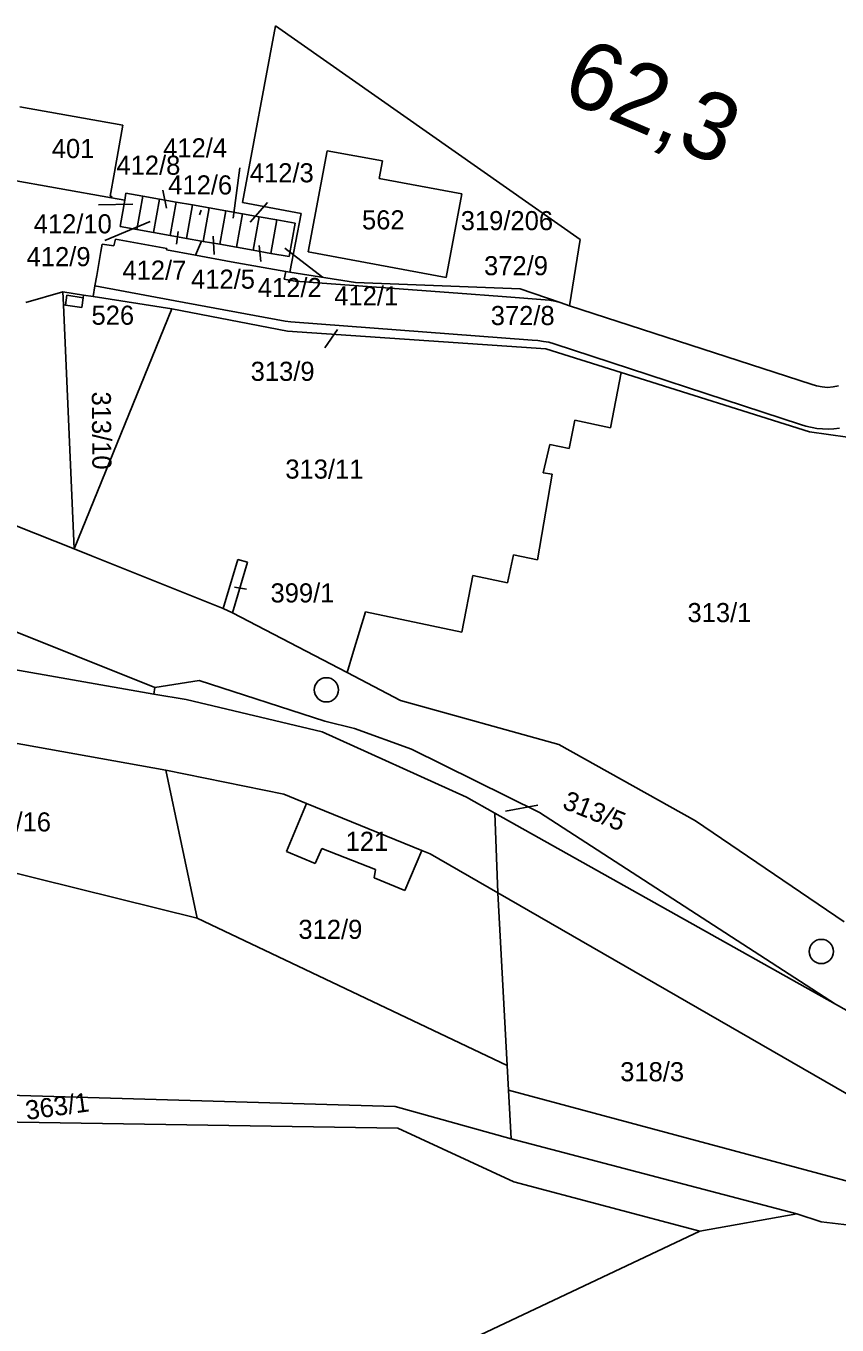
# Model space of a CAD drawing. Extents: x -805826 to -803822, y -1165880 to -1164382.
# Drawn here: x -805258.6 to -805114.2, y -1165078.1 to -1164846.8 of the extents above; entities that cross this region are included whole.
import ezdxf

# ---------------------------------------------------------------- set-up
doc = ezdxf.new("R2010")
doc.units = 0
for name, color, linetype in [('kilometráž - 2880', 7, 'Continuous'), ('kn_celek - Cisla parcel pomocna', 7, 'Continuous'), ('kn_celek - Cisla pozemkovych parcel', 7, 'Continuous'), ('kn_celek - Cisla stavebnich parcel', 7, 'Continuous'), ('kn_celek - Hranice parcel', 7, 'Continuous'), ('kn_celek - Vnitrni kresby', 7, 'Continuous'), ('plochy - SZDC', 7, 'Continuous')]:
    doc.layers.add(name, color=color, linetype=linetype)

msp = doc.modelspace()

# ---------------------------------------------------------------- linework, layer by layer
at = {"layer": 'kilometráž - 2880'}
for centre in [(-805205.12, -1164965.01), (-805117.01, -1165011.6)]:
    msp.add_circle(centre, 2.16, dxfattribs=at)
at = {"layer": 'kn_celek - Cisla parcel pomocna'}
for p, q in [((-805221.73, -1164881), (-805220.53, -1164872.06)), ((-805233.6, -1164879.25), (-805234.23, -1164876.02)), ((-805239.56, -1164878.53), (-805245.71, -1164878.63)), ((-805218.68, -1164881.73), (-805215.63, -1164878.22)), ((-805227.72, -1164880.44), (-805227.4, -1164879.59)), ((-805236.52, -1164881.64), (-805244.57, -1164885.01)), ((-805231.49, -1164883.37), (-805231.79, -1164885.66)), ((-805225.27, -1164884.21), (-805225.08, -1164887.5)), ((-805217.06, -1164885.88), (-805216.77, -1164888.73)), ((-805212.54, -1164886.36), (-805205.8, -1164891.53)), ((-805203.15, -1164900.87), (-805205.4, -1164904.12)), ((-805221.47, -1164946.71), (-805219.37, -1164947.07)), ((-805173.22, -1164986.64), (-805167.5, -1164985.52))]:
    msp.add_line(p, q, dxfattribs=at)
at = {"layer": 'kn_celek - Hranice parcel'}
for p, q in [((-805214.18, -1164846.8), (-805220.07, -1164878.24)), ((-805214.18, -1164846.8), (-805159.93, -1164884.85)), ((-805259.71, -1164861.19), (-805241.37, -1164864.44)), ((-805241.37, -1164864.44), (-805242.86, -1164872.82)), ((-805208.34, -1164887.04), (-805204.99, -1164869.01)), ((-805204.99, -1164869.01), (-805195.15, -1164870.83)), ((-805195.15, -1164870.83), (-805195.73, -1164873.93)), ((-805243.35, -1164877.38), (-805262, -1164874.09)), ((-805242.86, -1164872.82), (-805243.62, -1164877.13)), ((-805195.73, -1164873.93), (-805181, -1164876.67)), ((-805240.8, -1164876.56), (-805241.02, -1164877.84)), ((-805240.8, -1164876.56), (-805237.8, -1164877.09)), ((-805181, -1164876.67), (-805183.78, -1164891.59)), ((-805243.62, -1164877.13), (-805243.3, -1164877.19)), ((-805243.3, -1164877.19), (-805243.35, -1164877.38)), ((-805243.35, -1164877.38), (-805241.02, -1164877.84)), ((-805241.02, -1164877.84), (-805241.86, -1164882.53)), ((-805237.8, -1164877.09), (-805238.86, -1164883.05)), ((-805237.8, -1164877.09), (-805234.85, -1164877.62)), ((-805234.85, -1164877.62), (-805235.9, -1164883.57)), ((-805234.85, -1164877.62), (-805231.88, -1164878.15)), ((-805231.88, -1164878.15), (-805232.95, -1164884.11)), ((-805231.88, -1164878.15), (-805228.93, -1164878.67)), ((-805228.93, -1164878.67), (-805230, -1164884.63)), ((-805228.93, -1164878.67), (-805226, -1164879.2)), ((-805226, -1164879.2), (-805227.04, -1164885.15)), ((-805226, -1164879.2), (-805223.02, -1164879.73)), ((-805220.07, -1164878.24), (-805209.64, -1164880.21)), ((-805224.08, -1164885.68), (-805223.02, -1164879.73)), ((-805223.02, -1164879.73), (-805220.05, -1164880.25)), ((-805221.12, -1164886.2), (-805220.05, -1164880.25)), ((-805220.05, -1164880.25), (-805217.1, -1164880.78)), ((-805217.1, -1164880.78), (-805218.17, -1164886.72)), ((-805217.1, -1164880.78), (-805213.92, -1164881.34)), ((-805213.92, -1164881.34), (-805214.99, -1164887.29)), ((-805213.92, -1164881.34), (-805210.68, -1164881.9)), ((-805209.64, -1164880.21), (-805211.62, -1164890.64)), ((-805238.86, -1164883.05), (-805241.86, -1164882.53)), ((-805238.86, -1164883.05), (-805235.9, -1164883.57)), ((-805235.9, -1164883.57), (-805232.95, -1164884.11)), ((-805210.68, -1164881.9), (-805211.74, -1164887.86)), ((-805245.02, -1164885.65), (-805245.28, -1164886.98)), ((-805242.96, -1164885.95), (-805245.02, -1164885.65)), ((-805242.64, -1164884.75), (-805242.96, -1164885.95)), ((-805233.53, -1164886.43), (-805242.64, -1164884.75)), ((-805232.95, -1164884.11), (-805230, -1164884.63)), ((-805230, -1164884.63), (-805227.34, -1164885.1)), ((-805227.34, -1164885.1), (-805228.45, -1164887.59)), ((-805227.34, -1164885.1), (-805227.04, -1164885.15)), ((-805227.04, -1164885.15), (-805224.08, -1164885.68)), ((-805221.12, -1164886.2), (-805224.08, -1164885.68)), ((-805159.93, -1164884.85), (-805161.83, -1164896.62)), ((-805245.28, -1164886.98), (-805246.01, -1164891.26)), ((-805233.56, -1164886.64), (-805233.53, -1164886.43)), ((-805228.45, -1164887.59), (-805233.56, -1164886.64)), ((-805222.05, -1164888.77), (-805228.45, -1164887.59)), ((-805218.17, -1164886.72), (-805221.12, -1164886.2)), ((-805214.99, -1164887.29), (-805218.17, -1164886.72)), ((-805211.74, -1164887.86), (-805214.99, -1164887.29)), ((-805183.78, -1164891.59), (-805208.34, -1164887.04)), ((-805212.36, -1164890.52), (-805222.05, -1164888.77)), ((-805212.61, -1164891.87), (-805212.36, -1164890.52)), ((-805212.36, -1164890.52), (-805211.62, -1164890.64)), ((-805211.62, -1164890.64), (-805199.93, -1164892.46)), ((-805246.01, -1164891.26), (-805246.32, -1164893.09)), ((-805211.7, -1164892.07), (-805212.61, -1164891.87)), ((-805210.68, -1164892.23), (-805211.7, -1164892.07)), ((-805181.74, -1164894.4), (-805210.68, -1164892.23)), ((-805199.93, -1164892.46), (-805170.61, -1164893.62)), ((-805252.02, -1164894.15), (-805258.61, -1164896.04)), ((-805252.02, -1164894.15), (-805248.35, -1164894.73)), ((-805252.02, -1164894.15), (-805251.92, -1164896.44)), ((-805248.69, -1164896.92), (-805248.42, -1164895.21)), ((-805248.42, -1164895.21), (-805248.35, -1164894.73)), ((-805248.35, -1164894.73), (-805246.65, -1164894.99)), ((-805246.32, -1164893.09), (-805246.65, -1164894.99)), ((-805246.65, -1164894.99), (-805232.61, -1164897.19)), ((-805246.32, -1164893.09), (-805232.02, -1164895.74)), ((-805173.83, -1164895), (-805181.74, -1164894.4)), ((-805165.42, -1164895.64), (-805173.83, -1164895)), ((-805170.61, -1164893.62), (-805163.47, -1164896.06)), ((-805251.92, -1164896.44), (-805251.58, -1164896.49)), ((-805251.92, -1164896.44), (-805250.01, -1164939.9)), ((-805251.58, -1164896.49), (-805248.69, -1164896.92)), ((-805232.61, -1164897.19), (-805250.01, -1164939.9)), ((-805232.61, -1164897.19), (-805212.07, -1164901.15)), ((-805232.02, -1164895.74), (-805212.44, -1164899.38)), ((-805164.42, -1164895.79), (-805165.42, -1164895.64)), ((-805163.47, -1164896.06), (-805164.42, -1164895.79)), ((-805163.47, -1164896.06), (-805161.83, -1164896.62)), ((-805161.83, -1164896.62), (-805118.83, -1164910.59)), ((-805212.44, -1164899.38), (-805211.46, -1164899.5)), ((-805211.46, -1164899.5), (-805168.47, -1164902.75)), ((-805212.07, -1164901.15), (-805166.07, -1164904.28)), ((-805168.47, -1164902.75), (-805167.48, -1164902.83)), ((-805167.48, -1164902.83), (-805166.48, -1164902.96)), ((-805166.48, -1164902.96), (-805165.49, -1164903.12)), ((-805166.07, -1164904.28), (-805152.62, -1164908.51)), ((-805165.49, -1164903.12), (-805164.54, -1164903.4)), ((-805164.54, -1164903.4), (-805120.74, -1164917.78)), ((-805154.55, -1164918.33), (-805152.62, -1164908.51)), ((-805152.62, -1164908.51), (-805119.1, -1164919.05)), ((-805117.85, -1164910.85), (-805118.83, -1164910.59)), ((-805116.88, -1164911.06), (-805117.85, -1164910.85)), ((-805115.9, -1164911.16), (-805116.88, -1164911.06)), ((-805114.91, -1164911.08), (-805115.9, -1164911.16)), ((-805113.94, -1164910.87), (-805114.91, -1164911.08)), ((-805161.91, -1164922.02), (-805160.91, -1164916.98)), ((-805160.91, -1164916.98), (-805154.55, -1164918.33)), ((-805120.74, -1164917.78), (-805119.76, -1164918.06)), ((-805119.76, -1164918.06), (-805117.8, -1164918.46)), ((-805117.8, -1164918.46), (-805116.77, -1164918.56)), ((-805115.79, -1164918.57), (-805114.78, -1164918.51)), ((-805114.78, -1164918.51), (-805113.77, -1164918.39)), ((-805119.1, -1164919.05), (-805097.48, -1164922.09)), ((-805116.77, -1164918.56), (-805115.79, -1164918.57)), ((-805250.01, -1164939.9), (-805295.17, -1164922)), ((-805166.55, -1164926.35), (-805165.35, -1164921.35)), ((-805165.35, -1164921.35), (-805161.91, -1164922.02)), ((-805167.51, -1164941.87), (-805164.93, -1164926.63)), ((-805164.93, -1164926.63), (-805166.55, -1164926.35)), ((-805250.01, -1164939.9), (-805246.92, -1164941.14)), ((-805246.92, -1164941.14), (-805223.48, -1164950.53)), ((-805172.89, -1164945.97), (-805171.82, -1164940.97)), ((-805171.82, -1164940.97), (-805167.51, -1164941.87)), ((-805220.87, -1164941.82), (-805223.48, -1164950.53)), ((-805221.81, -1164951.29), (-805219.18, -1164942.25)), ((-805219.18, -1164942.25), (-805220.87, -1164941.82)), ((-805180.99, -1164954.75), (-805179.07, -1164944.63)), ((-805179.07, -1164944.63), (-805172.89, -1164945.97)), ((-805223.48, -1164950.53), (-805221.81, -1164951.29)), ((-805235.68, -1164964.57), (-805268.41, -1164951.46)), ((-805201.44, -1164961.95), (-805221.81, -1164951.29)), ((-805200.28, -1164958.11), (-805198.14, -1164951.1)), ((-805198.14, -1164951.1), (-805180.99, -1164954.75)), ((-805281.04, -1164957.84), (-805235.82, -1164965.77)), ((-805201.44, -1164961.95), (-805200.28, -1164958.11)), ((-805201.44, -1164961.95), (-805191.95, -1164966.91)), ((-805235.68, -1164964.57), (-805235.82, -1164965.77)), ((-805227.75, -1164963.37), (-805235.68, -1164964.57)), ((-805205.42, -1164970.56), (-805227.75, -1164963.37)), ((-805235.82, -1164965.77), (-805230.09, -1164966.74)), ((-805230.09, -1164966.74), (-805205.87, -1164972.46)), ((-805191.95, -1164966.91), (-805163.72, -1164974.75)), ((-805286.2, -1164969.87), (-805233.69, -1164979.3)), ((-805200.1, -1164971.91), (-805205.42, -1164970.56)), ((-805205.87, -1164972.46), (-805180.19, -1164984.13)), ((-805189.99, -1164975.59), (-805200.1, -1164971.91)), ((-805167.17, -1164986.87), (-805189.99, -1164975.59)), ((-805163.72, -1164974.75), (-805139.43, -1164988.32)), ((-805228.14, -1165005.65), (-805233.69, -1164979.3)), ((-805233.69, -1164979.3), (-805212.72, -1164983.59)), ((-805212.72, -1164983.59), (-805208.67, -1164985.24)), ((-805208.67, -1164985.24), (-805212.24, -1164993.81)), ((-805208.67, -1164985.24), (-805188.14, -1164993.59)), ((-805180.19, -1164984.13), (-805175.12, -1164986.98)), ((-805175.12, -1164986.98), (-805114.48, -1165020.99)), ((-805114.48, -1165020.99), (-805167.17, -1164986.87)), ((-805139.43, -1164988.32), (-805112.96, -1165006.31)), ((-805228.14, -1165005.65), (-805289.16, -1164990.57)), ((-805212.24, -1164993.81), (-805207.1, -1164995.93)), ((-805207.1, -1164995.93), (-805205.95, -1164993.27)), ((-805205.95, -1164993.27), (-805196.39, -1164997.01)), ((-805191.16, -1165000.76), (-805188.14, -1164993.59)), ((-805188.14, -1164993.59), (-805186.66, -1164994.19)), ((-805186.66, -1164994.19), (-805174.61, -1165001.14)), ((-805196.39, -1164997.01), (-805196.6, -1164998.49)), ((-805196.6, -1164998.49), (-805191.16, -1165000.76)), ((-805174.61, -1165001.14), (-805172.93, -1165031.88)), ((-805174.61, -1165001.14), (-805082.67, -1165054.14)), ((-805228.14, -1165005.65), (-805172.93, -1165031.88)), ((-805084.18, -1165037.92), (-805114.48, -1165020.99)), ((-805172.93, -1165031.88), (-805172.69, -1165036.29)), ((-805192.86, -1165039.19), (-805299.06, -1165036.1)), ((-805111.01, -1165052.83), (-805172.69, -1165036.29)), ((-805172.69, -1165036.29), (-805172.22, -1165044.95)), ((-805172.22, -1165044.95), (-805192.86, -1165039.19)), ((-805297.37, -1165041.45), (-805192.4, -1165043.05)), ((-805192.4, -1165043.05), (-805171.76, -1165052.61)), ((-805121.34, -1165058.34), (-805172.22, -1165044.95)), ((-805171.76, -1165052.61), (-805138.61, -1165061.4)), ((-805121.34, -1165058.34), (-805138.61, -1165061.4)), ((-805117.06, -1165059.74), (-805121.34, -1165058.34)), ((-805138.61, -1165061.4), (-805184.2, -1165082.97)), ((-805098.97, -1165061.86), (-805117.06, -1165059.74))]:
    msp.add_line(p, q, dxfattribs=at)
at = {"layer": 'kn_celek - Vnitrni kresby'}
for p, q in [((-805251.33, -1164894.76), (-805251.58, -1164896.49)), ((-805248.42, -1164895.21), (-805251.33, -1164894.76)), ((-805174.61, -1165001.14), (-805175.12, -1164986.98))]:
    msp.add_line(p, q, dxfattribs=at)
at = {"layer": 'plochy - SZDC'}
for p, q in [((-805250.01, -1164939.9), (-805295.17, -1164922)), ((-805246.92, -1164941.14), (-805250.01, -1164939.9)), ((-805223.48, -1164950.53), (-805246.92, -1164941.14)), ((-805221.81, -1164951.29), (-805223.48, -1164950.53)), ((-805268.41, -1164951.46), (-805235.68, -1164964.57)), ((-805201.44, -1164961.95), (-805221.81, -1164951.29)), ((-805191.95, -1164966.91), (-805201.44, -1164961.95)), ((-805235.68, -1164964.57), (-805227.75, -1164963.37)), ((-805227.75, -1164963.37), (-805205.42, -1164970.56)), ((-805163.72, -1164974.75), (-805191.95, -1164966.91)), ((-805205.42, -1164970.56), (-805200.1, -1164971.91)), ((-805200.1, -1164971.91), (-805189.99, -1164975.59)), ((-805189.99, -1164975.59), (-805167.17, -1164986.87)), ((-805139.43, -1164988.32), (-805163.72, -1164974.75)), ((-805167.17, -1164986.87), (-805114.48, -1165020.99)), ((-805112.96, -1165006.31), (-805139.43, -1164988.32)), ((-805114.48, -1165020.99), (-805084.18, -1165037.92))]:
    msp.add_line(p, q, dxfattribs=at)

# ---------------------------------------------------------------- texts
at = {"layer": 'kilometráž - 2880'}
msp.add_text('62,3', height=12, rotation=336.9207, dxfattribs=at).set_placement((-805163.68, -1164859.61))
at = {"layer": 'kn_celek - Cisla parcel pomocna'}
for s, p in [('412/4', (-805234.18, -1164870.2)), ('412/8', (-805242.5, -1164873.29)), ('412/3', (-805218.75, -1164874.64)), ('412/6', (-805233.28, -1164876.8)), ('412/10', (-805257.23, -1164883.73)), ('412/9', (-805258.49, -1164889.57)), ('412/7', (-805241.43, -1164891.97)), ('372/9', (-805177.05, -1164891.18)), ('412/5', (-805229.22, -1164893.58)), ('412/2', (-805217.33, -1164895.07)), ('412/1', (-805203.72, -1164896.56)), ('526', (-805246.94, -1164900)), ('313/9', (-805218.6, -1164909.99)), ('399/1', (-805215.07, -1164949.45))]:
    msp.add_text(s, height=3.4, dxfattribs=at).set_placement(p)
msp.add_text('313/5', height=3.4, rotation=338.157, dxfattribs=at).set_placement((-805163.3, -1164986.04))
at = {"layer": 'kn_celek - Cisla pozemkovych parcel'}
for s, height, p in [('319/206', 3.4, (-805181.2, -1164883.16)), ('372/9', 0.005, (-805174.52, -1164894.49)), ('372/8', 3.4, (-805175.86, -1164900.06)), ('313/9', 0.005, (-805203.15, -1164900.87)), ('313/11', 3.4, (-805212.43, -1164927.4)), ('399/1', 0.005, (-805221.47, -1164946.71)), ('313/1', 3.4, (-805140.83, -1164952.95)), ('312/16', 3.4, (-805268.06, -1164990.23)), ('313/5', 0.005, (-805173.22, -1164986.64)), ('312/9', 3.4, (-805210.1, -1165009.36)), ('318/3', 3.4, (-805152.81, -1165034.71))]:
    msp.add_text(s, height=height, dxfattribs=at).set_placement(p)
for s, rotation, p in [('313/10', 270.432, (-805246.89, -1164911.9)), ('363/1', 7.848, (-805258.46, -1165041.61))]:
    msp.add_text(s, height=3.4, rotation=rotation, dxfattribs=at).set_placement(p)
at = {"layer": 'kn_celek - Cisla stavebnich parcel'}
for s, height, p in [('401', 3.4, (-805254.01, -1164870.32)), ('412/10', 0.005, (-805239.56, -1164878.53)), ('412/8', 0.005, (-805233.6, -1164879.25)), ('412/6', 0.005, (-805227.72, -1164880.44)), ('412/4', 0.005, (-805221.73, -1164881)), ('562', 3.4, (-805198.78, -1164883.02)), ('412/9', 0.005, (-805236.52, -1164881.64)), ('412/7', 0.005, (-805231.49, -1164883.37)), ('412/3', 0.005, (-805218.68, -1164881.73)), ('412/5', 0.005, (-805225.27, -1164884.21)), ('412/2', 0.005, (-805217.06, -1164885.88)), ('412/1', 0.005, (-805212.54, -1164886.36)), ('526', 0.005, (-805249.32, -1164896.18)), ('121', 3.4, (-805201.7, -1164993.68))]:
    msp.add_text(s, height=height, dxfattribs=at).set_placement(p)

doc.saveas('drawing.dxf')
